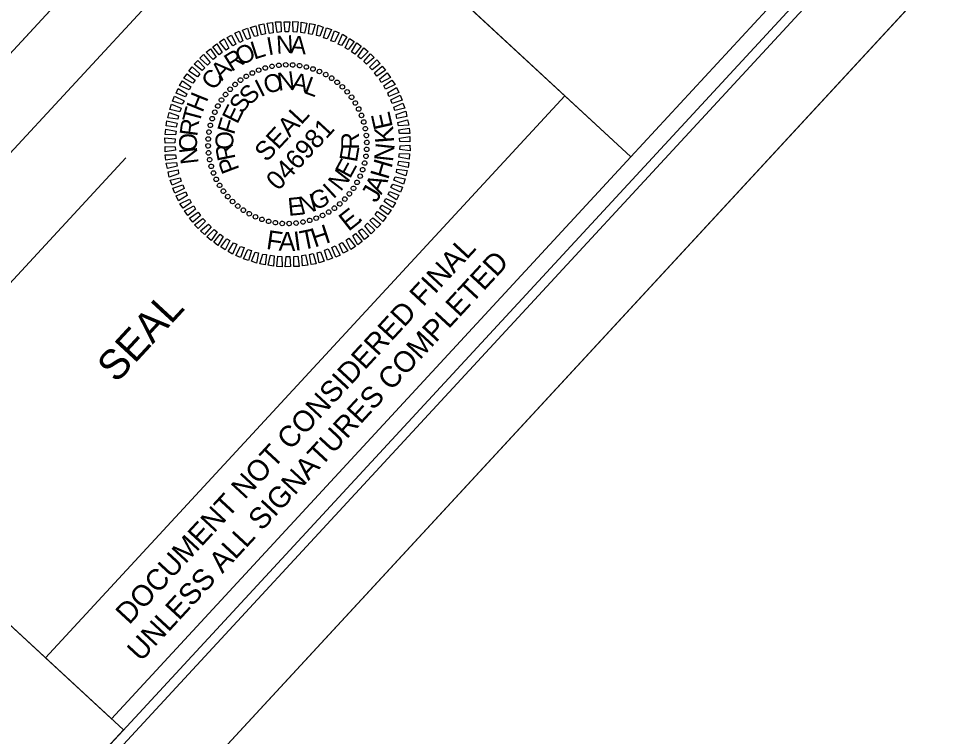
# Model space of a CAD drawing. Extents: x 1767460 to 1770129, y 996106 to 1001438.
# Drawn here: x 1769606.3 to 1769898.5, y 1000044.7 to 1000271.5 of the extents above; entities that cross this region are included whole.
import ezdxf

# ---------------------------------------------------------------- set-up
doc = ezdxf.new("R2010")
doc.units = 0
for name, color, linetype in [('Draft_RDY_Construction', 7, 'Continuous'), ('E_NCDOT_Terrain_Model_Contour_Minor', 7, 'Continuous'), ('E_NCDOT_Terrain_Model_Points_Low', 7, 'Continuous'), ('E_NCDOT_Terrain_Model_Triangle_Vertices', 7, 'Continuous'), ('P_NCDOT_Terrain_Points_High', 7, 'Continuous'), ('P_RDY_TC_Surface_Grass', 7, 'Continuous'), ('P_RDY_TL_Edge_of_Travel', 7, 'Continuous')]:
    doc.layers.add(name, color=color, linetype=linetype)

msp = doc.modelspace()

# ---------------------------------------------------------------- linework, layer by layer
at = {"layer": 'E_NCDOT_Terrain_Model_Contour_Minor'}
msp.add_lwpolyline([(1768744.05, 999038.07), (1770128.77, 1000536.12), (1769152.55, 1001438.49), (1767767.83, 999940.44)], close=True, dxfattribs=at)
at = {"layer": 'E_NCDOT_Terrain_Model_Points_Low'}
msp.add_lwpolyline([(1767804.38, 999935.46), (1769171.05, 1001413.98), (1770107.33, 1000548.53), (1768740.66, 999070.01)], close=True, dxfattribs=at)
at = {"layer": 'E_NCDOT_Terrain_Model_Triangle_Vertices'}
for p, q in [((1769569.13, 1000191.69), (1769689.18, 1000321.56)), ((1769698.57, 1000321.36), (1769799.74, 1000227.84)), ((1769574.75, 1000156.68), (1769640.2, 1000227.49))]:
    msp.add_line(p, q, dxfattribs=at)
for points in [[(1769163.02, 1001400.87), (1767932.52, 1000069.67), (1768864.37, 999208.32), (1770094.87, 1000539.52)], [(1769677.71, 1000340.64), (1769771.23, 1000441.81), (1769893.26, 1000329.01), (1769799.74, 1000227.84)], [(1769513.61, 1000163.11), (1769677.71, 1000340.64), (1769799.74, 1000227.84), (1769635.64, 1000050.31)]]:
    msp.add_lwpolyline(points, close=True, dxfattribs=at)
at = {"layer": 'P_NCDOT_Terrain_Points_High'}
msp.add_line((1768744.05, 999038.07), (1770128.77, 1000536.12), dxfattribs=at)
msp.add_lwpolyline([(1769163.02, 1001400.87), (1767932.52, 1000069.67), (1768864.37, 999208.32), (1769639.43, 1000046.81), (1769513.61, 1000163.11), (1769964.83, 1000651.25), (1769968.19, 1000656.62)], close=True, dxfattribs=at)
at = {"layer": 'P_RDY_TC_Surface_Grass'}
for p, q in [((1769686.37, 1000256.43), (1769686.37, 1000256.43)), ((1769688.55, 1000256.8), (1769688.55, 1000256.8)), ((1769690.7, 1000256.92), (1769690.7, 1000256.92)), ((1769692.93, 1000256.9), (1769692.93, 1000256.9)), ((1769695.06, 1000256.63), (1769695.06, 1000256.63)), ((1769680.15, 1000254.35), (1769680.15, 1000254.35)), ((1769682.17, 1000255.21), (1769682.17, 1000255.21)), ((1769684.23, 1000255.96), (1769684.23, 1000255.96)), ((1769697.24, 1000256.19), (1769697.24, 1000256.19)), ((1769699.35, 1000255.6), (1769699.35, 1000255.6)), ((1769701.36, 1000254.83), (1769701.36, 1000254.83)), ((1769703.31, 1000253.85), (1769703.31, 1000253.85)), ((1769674.74, 1000250.71), (1769674.74, 1000250.71)), ((1769676.46, 1000252.05), (1769676.46, 1000252.05)), ((1769678.21, 1000253.28), (1769678.21, 1000253.28)), ((1769705.2, 1000252.65), (1769705.2, 1000252.65)), ((1769706.98, 1000251.41), (1769706.98, 1000251.41)), ((1769671.68, 1000247.54), (1769671.68, 1000247.54)), ((1769673.14, 1000249.19), (1769673.14, 1000249.19)), ((1769708.63, 1000249.95), (1769708.63, 1000249.95)), ((1769710.14, 1000248.35), (1769710.14, 1000248.35)), ((1769670.44, 1000245.76), (1769670.44, 1000245.76)), ((1769711.49, 1000246.63), (1769711.49, 1000246.63)), ((1769712.72, 1000244.87), (1769712.72, 1000244.87)), ((1769668.26, 1000241.92), (1769668.26, 1000241.92)), ((1769669.24, 1000243.87), (1769669.24, 1000243.87)), ((1769713.79, 1000242.93), (1769713.79, 1000242.93)), ((1769667.49, 1000239.91), (1769667.49, 1000239.91)), ((1769714.65, 1000240.92), (1769714.65, 1000240.92)), ((1769715.4, 1000238.86), (1769715.4, 1000238.86)), ((1769666.9, 1000237.8), (1769666.9, 1000237.8)), ((1769715.87, 1000236.72), (1769715.87, 1000236.72)), ((1769666.18, 1000233.49), (1769666.18, 1000233.49)), ((1769666.45, 1000235.63), (1769666.45, 1000235.63)), ((1769716.24, 1000234.54), (1769716.24, 1000234.54)), ((1769666.16, 1000231.26), (1769666.16, 1000231.26)), ((1769691.26, 1000231.82), (1769691.26, 1000231.82)), ((1769716.34, 1000230.16), (1769716.34, 1000230.16)), ((1769716.36, 1000232.39), (1769716.36, 1000232.39)), ((1769666.28, 1000229.11), (1769666.28, 1000229.11)), ((1769716.07, 1000228.02), (1769716.07, 1000228.02)), ((1769666.65, 1000226.93), (1769666.65, 1000226.93)), ((1769667.13, 1000224.79), (1769667.13, 1000224.79)), ((1769715.63, 1000225.85), (1769715.63, 1000225.85)), ((1769667.88, 1000222.73), (1769667.88, 1000222.73)), ((1769714.27, 1000221.72), (1769714.27, 1000221.72)), ((1769715.04, 1000223.74), (1769715.04, 1000223.74)), ((1769668.74, 1000220.71), (1769668.74, 1000220.71)), ((1769669.8, 1000218.77), (1769669.8, 1000218.77)), ((1769713.28, 1000219.77), (1769713.28, 1000219.77)), ((1769671.04, 1000217.02), (1769671.04, 1000217.02)), ((1769710.85, 1000216.11), (1769710.85, 1000216.11)), ((1769712.09, 1000217.89), (1769712.09, 1000217.89)), ((1769672.38, 1000215.3), (1769672.38, 1000215.3)), ((1769673.89, 1000213.7), (1769673.89, 1000213.7)), ((1769707.79, 1000212.94), (1769707.79, 1000212.94)), ((1769709.39, 1000214.46), (1769709.39, 1000214.46)), ((1769675.54, 1000212.24), (1769675.54, 1000212.24)), ((1769677.33, 1000211), (1769677.33, 1000211)), ((1769679.21, 1000209.8), (1769679.21, 1000209.8)), ((1769704.31, 1000210.36), (1769704.31, 1000210.36)), ((1769706.07, 1000211.6), (1769706.07, 1000211.6)), ((1769681.16, 1000208.82), (1769681.16, 1000208.82)), ((1769683.18, 1000208.05), (1769683.18, 1000208.05)), ((1769685.29, 1000207.46), (1769685.29, 1000207.46)), ((1769687.46, 1000207.01), (1769687.46, 1000207.01)), ((1769689.6, 1000206.74), (1769689.6, 1000206.74)), ((1769691.83, 1000206.72), (1769691.83, 1000206.72)), ((1769693.98, 1000206.84), (1769693.98, 1000206.84)), ((1769696.16, 1000207.21), (1769696.16, 1000207.21)), ((1769698.3, 1000207.69), (1769698.3, 1000207.69)), ((1769700.36, 1000208.44), (1769700.36, 1000208.44)), ((1769702.37, 1000209.3), (1769702.37, 1000209.3))]:
    msp.add_line(p, q, dxfattribs=at)
for points in [[(1769678.39, 1000264.9), (1769677.07, 1000267.82), (1769678.64, 1000268.48), (1769679.54, 1000265.33)], [(1769680.8, 1000265.8), (1769679.62, 1000268.73), (1769681.26, 1000269.25), (1769681.88, 1000266.09)], [(1769683.11, 1000266.32), (1769682.17, 1000269.57), (1769683.83, 1000269.82), (1769684.3, 1000266.72)], [(1769685.61, 1000266.81), (1769684.84, 1000270.03), (1769686.53, 1000270.24), (1769686.77, 1000267.03)], [(1769688.03, 1000267.15), (1769687.52, 1000270.42), (1769689.21, 1000270.49), (1769689.23, 1000267.34)], [(1769690.54, 1000267.28), (1769690.27, 1000270.46), (1769691.97, 1000270.52), (1769691.64, 1000267.29)], [(1769693.05, 1000267.35), (1769692.96, 1000270.56), (1769694.66, 1000270.42), (1769694.26, 1000267.18)], [(1769695.5, 1000267.13), (1769695.62, 1000270.35), (1769697.33, 1000270.06), (1769696.61, 1000266.92)], [(1769697.89, 1000266.69), (1769698.29, 1000269.92), (1769700.04, 1000269.6), (1769699.1, 1000266.52)], [(1769700.39, 1000266.15), (1769701, 1000269.39), (1769702.58, 1000268.82), (1769701.49, 1000265.95)], [(1769702.64, 1000265.42), (1769703.55, 1000268.61), (1769705.16, 1000268), (1769703.79, 1000265.05)], [(1769671.87, 1000261.53), (1769669.83, 1000264.1), (1769671.27, 1000265.08), (1769672.77, 1000262.13)], [(1769673.98, 1000262.85), (1769672.21, 1000265.5), (1769673.63, 1000266.3), (1769674.95, 1000263.38)], [(1769676.17, 1000263.89), (1769674.64, 1000266.87), (1769676.03, 1000267.49), (1769677.21, 1000264.5)], [(1769704.98, 1000264.49), (1769706.1, 1000267.61), (1769707.61, 1000266.96), (1769706.09, 1000264.14)], [(1769707.29, 1000263.45), (1769708.61, 1000266.58), (1769710.03, 1000265.68), (1769708.3, 1000262.99)], [(1769709.46, 1000262.26), (1769710.9, 1000265.22), (1769712.35, 1000264.28), (1769710.43, 1000261.77)], [(1769669.74, 1000260.03), (1769667.69, 1000262.53), (1769669, 1000263.57), (1769670.66, 1000260.81)], [(1769711.52, 1000260.96), (1769713.22, 1000263.82), (1769714.57, 1000262.78), (1769712.54, 1000260.29)], [(1769713.49, 1000259.55), (1769715.4, 1000262.21), (1769716.72, 1000261.13), (1769714.44, 1000258.81)], [(1769666.01, 1000256.8), (1769663.62, 1000259.01), (1769664.78, 1000260.19), (1769666.86, 1000257.65)], [(1769667.82, 1000258.54), (1769665.56, 1000260.89), (1769666.91, 1000261.9), (1769668.78, 1000259.28)], [(1769715.36, 1000257.89), (1769717.46, 1000260.38), (1769718.7, 1000259.23), (1769716.24, 1000257.08)], [(1769664.34, 1000255.07), (1769661.79, 1000257.1), (1769662.94, 1000258.27), (1769665.19, 1000255.92)], [(1769717.16, 1000256.16), (1769719.44, 1000258.48), (1769720.58, 1000257.28), (1769717.98, 1000255.27)], [(1769718.75, 1000254.35), (1769721.15, 1000256.49), (1769722.26, 1000255.19), (1769719.47, 1000253.35)], [(1769661.42, 1000251.1), (1769658.53, 1000252.69), (1769659.54, 1000254), (1769662.12, 1000252.08)], [(1769662.83, 1000253.07), (1769660.11, 1000254.84), (1769661.11, 1000256.22), (1769663.53, 1000254.05)], [(1769720.36, 1000252.32), (1769722.75, 1000254.33), (1769723.76, 1000252.92), (1769720.85, 1000251.32)], [(1769660.2, 1000248.97), (1769657.17, 1000250.33), (1769658.07, 1000251.82), (1769660.72, 1000249.91)], [(1769721.68, 1000250.22), (1769724.26, 1000252.05), (1769725.23, 1000250.67), (1769722.18, 1000249.21)], [(1769659.04, 1000246.76), (1769656.06, 1000247.95), (1769656.78, 1000249.4), (1769659.5, 1000247.77)], [(1769722.93, 1000248.04), (1769725.7, 1000249.7), (1769726.39, 1000248.17), (1769723.33, 1000246.92)], [(1769657.97, 1000244.42), (1769654.96, 1000245.43), (1769655.53, 1000246.94), (1769658.6, 1000245.54)], [(1769723.87, 1000245.81), (1769726.82, 1000247.3), (1769727.44, 1000245.7), (1769724.34, 1000244.69)], [(1769724.88, 1000243.51), (1769727.73, 1000244.76), (1769728.36, 1000243.15), (1769725.17, 1000242.43)], [(1769656.67, 1000239.7), (1769653.43, 1000240.17), (1769653.89, 1000241.85), (1769656.87, 1000240.8)], [(1769657.25, 1000242.09), (1769654.1, 1000242.82), (1769654.64, 1000244.43), (1769657.66, 1000243.21)], [(1769725.64, 1000241.17), (1769728.64, 1000242.21), (1769728.99, 1000240.53), (1769725.76, 1000239.97)], [(1769656.09, 1000237.23), (1769652.96, 1000237.61), (1769653.15, 1000239.21), (1769656.4, 1000238.45)], [(1769726.09, 1000238.71), (1769729.17, 1000239.54), (1769729.59, 1000237.86), (1769726.35, 1000237.59)], [(1769655.9, 1000234.82), (1769652.68, 1000234.87), (1769652.83, 1000236.58), (1769656.07, 1000235.96)], [(1769726.47, 1000236.32), (1769729.67, 1000236.91), (1769729.87, 1000235.22), (1769726.65, 1000235.2)], [(1769655.68, 1000232.3), (1769652.58, 1000232.18), (1769652.51, 1000233.87), (1769655.82, 1000233.47)], [(1769726.68, 1000233.75), (1769729.91, 1000234.23), (1769729.91, 1000232.53), (1769726.72, 1000232.62)], [(1769655.85, 1000229.9), (1769652.61, 1000229.42), (1769652.62, 1000231.12), (1769655.81, 1000231.03)], [(1769726.84, 1000231.35), (1769729.95, 1000231.47), (1769730.02, 1000229.77), (1769726.71, 1000230.17)], [(1769656.06, 1000227.33), (1769652.86, 1000226.74), (1769652.65, 1000228.43), (1769655.87, 1000228.45)], [(1769726.62, 1000228.83), (1769729.84, 1000228.78), (1769729.7, 1000227.07), (1769726.45, 1000227.69)], [(1769656.43, 1000224.93), (1769653.35, 1000224.11), (1769652.93, 1000225.79), (1769656.18, 1000226.06)], [(1769726.43, 1000226.41), (1769729.56, 1000226.04), (1769729.38, 1000224.44), (1769726.13, 1000225.2)], [(1769656.88, 1000222.48), (1769653.88, 1000221.44), (1769653.53, 1000223.12), (1769656.77, 1000223.67)], [(1769657.65, 1000220.14), (1769654.8, 1000218.89), (1769654.17, 1000220.49), (1769657.36, 1000221.22)], [(1769725.28, 1000221.56), (1769728.42, 1000220.83), (1769727.88, 1000219.22), (1769724.86, 1000220.44)], [(1769725.86, 1000223.95), (1769729.1, 1000223.47), (1769728.63, 1000221.79), (1769725.65, 1000222.84)], [(1769658.66, 1000217.84), (1769655.71, 1000216.34), (1769655.08, 1000217.95), (1769658.19, 1000218.95)], [(1769724.56, 1000219.23), (1769727.57, 1000218.21), (1769726.99, 1000216.7), (1769723.93, 1000218.11)], [(1769659.6, 1000215.61), (1769656.83, 1000213.95), (1769656.13, 1000215.48), (1769659.2, 1000216.73)], [(1769723.48, 1000216.89), (1769726.47, 1000215.69), (1769725.74, 1000214.25), (1769723.03, 1000215.88)], [(1769660.85, 1000213.43), (1769658.27, 1000211.6), (1769657.29, 1000212.97), (1769660.35, 1000214.44)], [(1769721.11, 1000212.55), (1769724, 1000210.96), (1769722.99, 1000209.65), (1769720.4, 1000211.56)], [(1769722.33, 1000214.68), (1769725.36, 1000213.31), (1769724.46, 1000211.83), (1769721.8, 1000213.74)], [(1769662.17, 1000211.33), (1769659.77, 1000209.32), (1769658.76, 1000210.73), (1769661.67, 1000212.33)], [(1769663.77, 1000209.3), (1769661.38, 1000207.15), (1769660.27, 1000208.46), (1769663.06, 1000210.3)], [(1769719.7, 1000210.58), (1769722.42, 1000208.81), (1769721.41, 1000207.43), (1769718.99, 1000209.6)], [(1769665.36, 1000207.49), (1769663.08, 1000205.17), (1769661.94, 1000206.36), (1769664.55, 1000208.38)], [(1769716.52, 1000206.85), (1769718.9, 1000204.64), (1769717.75, 1000203.46), (1769715.67, 1000206)], [(1769718.18, 1000208.57), (1769720.74, 1000206.55), (1769719.58, 1000205.37), (1769717.33, 1000207.73)], [(1769667.17, 1000205.75), (1769665.07, 1000203.27), (1769663.82, 1000204.42), (1769666.28, 1000206.57)], [(1769669.04, 1000204.09), (1769667.12, 1000201.44), (1769665.81, 1000202.52), (1769668.09, 1000204.84)], [(1769714.71, 1000205.11), (1769716.96, 1000202.76), (1769715.62, 1000201.75), (1769713.75, 1000204.37)], [(1769671, 1000202.69), (1769669.31, 1000199.82), (1769667.96, 1000200.87), (1769669.98, 1000203.35)], [(1769673.07, 1000201.39), (1769671.63, 1000198.43), (1769670.18, 1000199.36), (1769672.1, 1000201.88)], [(1769708.55, 1000200.8), (1769710.31, 1000198.15), (1769708.89, 1000197.35), (1769707.58, 1000200.27)], [(1769710.65, 1000202.12), (1769712.7, 1000199.55), (1769711.25, 1000198.57), (1769709.76, 1000201.52)], [(1769712.79, 1000203.62), (1769714.83, 1000201.12), (1769713.53, 1000200.08), (1769711.86, 1000202.84)], [(1769675.24, 1000200.2), (1769673.91, 1000197.07), (1769672.5, 1000197.97), (1769674.23, 1000200.65)], [(1769677.54, 1000199.16), (1769676.43, 1000196.03), (1769674.92, 1000196.68), (1769676.43, 1000199.5)], [(1769679.88, 1000198.22), (1769678.98, 1000195.04), (1769677.36, 1000195.65), (1769678.73, 1000198.6)], [(1769701.73, 1000197.84), (1769702.9, 1000194.92), (1769701.26, 1000194.39), (1769700.64, 1000197.55)], [(1769704.13, 1000198.75), (1769705.45, 1000195.83), (1769703.88, 1000195.17), (1769702.98, 1000198.32)], [(1769706.36, 1000199.76), (1769707.89, 1000196.78), (1769706.5, 1000196.16), (1769705.32, 1000199.15)], [(1769682.14, 1000197.5), (1769681.52, 1000194.25), (1769679.94, 1000194.83), (1769681.03, 1000197.7)], [(1769684.64, 1000196.96), (1769684.23, 1000193.72), (1769682.49, 1000194.04), (1769683.43, 1000197.12)], [(1769687.02, 1000196.52), (1769686.9, 1000193.3), (1769685.19, 1000193.58), (1769685.92, 1000196.73)], [(1769689.47, 1000196.3), (1769689.57, 1000193.08), (1769687.86, 1000193.23), (1769688.27, 1000196.46)], [(1769691.98, 1000196.36), (1769692.25, 1000193.19), (1769690.56, 1000193.12), (1769690.89, 1000196.36)], [(1769694.49, 1000196.5), (1769695.01, 1000193.23), (1769693.31, 1000193.16), (1769693.3, 1000196.31)], [(1769696.92, 1000196.84), (1769697.68, 1000193.62), (1769695.99, 1000193.41), (1769695.76, 1000196.62)], [(1769699.41, 1000197.33), (1769700.35, 1000194.07), (1769698.7, 1000193.83), (1769698.23, 1000196.93)]]:
    msp.add_lwpolyline(points, close=True, dxfattribs=at)
for centre, major_axis in [((1769684.24, 1000255.9), (-0.201, 0.691)), ((1769686.37, 1000256.42), (-0.14, 0.706)), ((1769688.53, 1000256.75), (-0.078, 0.716)), ((1769690.72, 1000256.9), (-0.016, 0.72)), ((1769692.9, 1000256.85), (0.047, 0.718)), ((1769695.08, 1000256.61), (0.11, 0.712)), ((1769697.22, 1000256.19), (0.171, 0.699)), ((1769699.32, 1000255.57), (0.231, 0.682)), ((1769678.25, 1000253.26), (-0.374, 0.616)), ((1769680.17, 1000254.32), (-0.318, 0.646)), ((1769682.17, 1000255.2), (-0.261, 0.671)), ((1769701.36, 1000254.78), (0.29, 0.659)), ((1769703.33, 1000253.81), (0.346, 0.631)), ((1769705.2, 1000252.68), (0.4, 0.599)), ((1769674.73, 1000250.68), (-0.475, 0.541)), ((1769676.43, 1000252.05), (-0.426, 0.581)), ((1769706.96, 1000251.38), (0.451, 0.562)), ((1769708.61, 1000249.94), (0.498, 0.52)), ((1769671.7, 1000247.52), (-0.562, 0.451)), ((1769673.15, 1000249.17), (-0.52, 0.498)), ((1769710.12, 1000248.36), (0.541, 0.475)), ((1769669.27, 1000243.89), (-0.631, 0.346)), ((1769670.41, 1000245.76), (-0.599, 0.4)), ((1769711.49, 1000246.65), (0.581, 0.426)), ((1769712.7, 1000244.84), (0.616, 0.374)), ((1769668.31, 1000241.92), (-0.659, 0.29)), ((1769713.76, 1000242.92), (0.646, 0.318)), ((1769714.64, 1000240.91), (0.671, 0.261)), ((1769667.51, 1000239.88), (-0.682, 0.231)), ((1769715.34, 1000238.84), (0.691, 0.201)), ((1769666.47, 1000235.64), (-0.712, 0.11)), ((1769666.9, 1000237.78), (-0.699, 0.171)), ((1769715.86, 1000236.72), (0.706, 0.14)), ((1769666.24, 1000233.46), (-0.718, 0.047)), ((1769716.19, 1000234.55), (0.716, 0.078)), ((1769716.34, 1000232.37), (0.72, 0.016)), ((1769666.19, 1000231.28), (-0.72, -0.016)), ((1769716.29, 1000230.18), (0.718, -0.047)), ((1769666.33, 1000229.09), (-0.716, -0.078)), ((1769666.66, 1000226.93), (-0.706, -0.14)), ((1769716.05, 1000228.01), (0.712, -0.11)), ((1769667.19, 1000224.81), (-0.691, -0.201)), ((1769715.01, 1000223.76), (0.682, -0.231)), ((1769715.62, 1000225.86), (0.699, -0.171)), ((1769667.89, 1000222.73), (-0.671, -0.261)), ((1769668.77, 1000220.73), (-0.646, -0.318)), ((1769714.22, 1000221.72), (0.659, -0.29)), ((1769669.82, 1000218.81), (-0.616, -0.374)), ((1769712.12, 1000217.89), (0.599, -0.4)), ((1769713.25, 1000219.76), (0.631, -0.346)), ((1769671.04, 1000216.99), (-0.581, -0.426)), ((1769672.41, 1000215.29), (-0.541, -0.475)), ((1769710.82, 1000216.13), (0.562, -0.451)), ((1769673.92, 1000213.71), (-0.498, -0.52)), ((1769675.57, 1000212.26), (-0.451, -0.562)), ((1769707.8, 1000212.97), (0.475, -0.541)), ((1769709.38, 1000214.48), (0.52, -0.498)), ((1769677.33, 1000210.97), (-0.4, -0.599)), ((1769679.2, 1000209.84), (-0.346, -0.631)), ((1769681.16, 1000208.87), (-0.29, -0.659)), ((1769702.36, 1000209.33), (0.318, -0.646)), ((1769704.27, 1000210.38), (0.374, -0.616)), ((1769706.09, 1000211.6), (0.426, -0.581)), ((1769683.2, 1000208.07), (-0.231, -0.682)), ((1769685.3, 1000207.46), (-0.171, -0.699)), ((1769687.45, 1000207.04), (-0.11, -0.712)), ((1769689.62, 1000206.8), (-0.047, -0.718)), ((1769691.81, 1000206.75), (0.016, -0.72)), ((1769693.99, 1000206.89), (0.078, -0.716)), ((1769696.16, 1000207.23), (0.14, -0.706)), ((1769698.28, 1000207.75), (0.201, -0.691)), ((1769700.35, 1000208.45), (0.261, -0.671))]:
    msp.add_ellipse(centre, major_axis=major_axis, ratio=0.999708, dxfattribs=at)
at = {"layer": 'P_RDY_TL_Edge_of_Travel'}
for p, q in [((1769614.79, 1000069.59), (1769778.88, 1000247.12)), ((1769778.9, 1000247.11), (1769799.75, 1000227.83)), ((1769799.74, 1000227.84), (1769635.64, 1000050.31)), ((1769635.64, 1000050.31), (1769614.79, 1000069.59))]:
    msp.add_line(p, q, dxfattribs=at)

# ---------------------------------------------------------------- texts
at = {"layer": 'Draft_RDY_Construction'}
msp.add_text('SEAL', height=9.441, rotation=47.2512, dxfattribs=at).set_placement((1769637.23, 1000156.1))
at = {"layer": 'P_RDY_TC_Surface_Grass'}
for s, height, rotation, p in [('I', 5.64, 10.2714, (1769685.24, 1000259.86)), ('N', 5.64, 3.0701, (1769687.84, 1000260.38)), ('A', 5.64, 355.8684, (1769692.01, 1000260.55)), ('O', 5.64, 24.6724, (1769676.39, 1000256.54)), ('L', 5.64, 17.4721, (1769680.73, 1000258.51)), ('R', 5.64, 31.8723, (1769673.56, 1000254.59)), ('A', 5.64, 46.2715, (1769670.56, 1000251.64)), ('C', 5.64, 53.4711, (1769668.1, 1000248.53)), ('O', 5.64, 17.0847, (1769684.7, 1000247.56)), ('N', 5.64, 7.7278, (1769688.44, 1000248.66)), ('A', 5.64, 349.0115, (1769692.29, 1000248.99)), ('S', 5.64, 45.1516, (1769679.4, 1000243.88)), ('I', 5.64, 26.4408, (1769682.83, 1000246.57)), ('L', 5.64, 339.6521, (1769696.14, 1000248.08)), ('H', 5.64, 67.8707, (1769664.41, 1000241.6)), ('S', 5.64, 54.5068, (1769676.99, 1000241.21)), ('T', 5.64, 75.071, (1769663.42, 1000238.09)), ('E', 5.64, 63.8623, (1769675.42, 1000237.96)), ('SEAL', 5.998, 47.2512, (1769684.67, 1000225.94)), ('E', 6, 102.7443, (1769724.59, 1000237.25)), ('R', 5.64, 82.2717, (1769662.73, 1000234.1)), ('F', 5.64, 73.2183, (1769674.35, 1000234.59)), ('046981', 5.998, 47.2512, (1769688.34, 1000216.86)), ('K', 6, 94.4603, (1769725.02, 1000232.39)), ('O', 5.64, 89.473, (1769662.66, 1000229.46)), ('O', 5.64, 91.9325, (1769674.27, 1000230.17)), ('R', 5.64, 89.7326, (1769713.87, 1000230.13)), ('N', 5.64, 96.6747, (1769663.23, 1000225.8)), ('R', 5.64, 101.2909, (1769674.88, 1000227.22)), ('E', 5.64, 80.3753, (1769713.18, 1000225.93)), ('N', 6, 83.7345, (1769724.54, 1000226.09)), ('P', 5.64, 110.6501, (1769676.15, 1000223.87)), ('E', 5.64, 61.663, (1769711.02, 1000220.71)), ('H', 6, 73.7505, (1769723.04, 1000220.41)), ('N', 5.64, 52.3076, (1769708.1, 1000216.67)), ('I', 5.64, 42.9524, (1769705.72, 1000214.31)), ('J', 6, 59.6524, (1769719.3, 1000213.02)), ('A', 6, 64.9102, (1769720.91, 1000215.66)), ('N', 5.64, 14.8852, (1769695.64, 1000209.53)), ('G', 5.64, 24.2415, (1769699.87, 1000210.79)), ('E', 5.64, 5.5281, (1769691.62, 1000209.16)), ('E', 6, 38.3089, (1769710.53, 1000204.1)), ('.', 6, 45.4183, (1769713.82, 1000206.7)), ('F', 6, 351.6655, (1769684.34, 1000198.78)), ('A', 6, 358.6821, (1769688.42, 1000198.18)), ('I', 6, 7.5224, (1769693.63, 1000198.14)), ('T', 6, 11.3243, (1769695.86, 1000198.37)), ('H', 6, 18.1246, (1769699.79, 1000199.15))]:
    msp.add_text(s, height=height, rotation=rotation, dxfattribs=at).set_placement(p)
at = {"layer": 'P_RDY_TL_Edge_of_Travel'}
for s, p in [('DOCUMENT NOT CONSIDERED FINAL', (1769641.25, 1000079.8)), ('UNLESS ALL SIGNATURES COMPLETED', (1769644.9, 1000068.08))]:
    msp.add_text(s, height=6.6469, rotation=47.2512, dxfattribs=at).set_placement(p)

doc.saveas('drawing.dxf')
